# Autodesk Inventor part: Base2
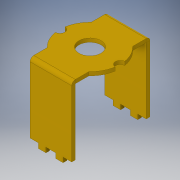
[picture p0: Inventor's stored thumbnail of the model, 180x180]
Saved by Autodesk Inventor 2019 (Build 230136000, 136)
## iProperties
Created: 2019-04
Part Number: Base2
Material: Generic
Document SubType Name: Sheet Metal
Designer: Plo
Density: 1 g/cm^3
Sheet Metal Rule: Default_mm
Appearance: Gold
Author: Plo
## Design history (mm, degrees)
node "Face1"
  sketch "Sketch1"
    geometry: L1 (-8.5, 14.5)-(8.5, 14.5); L2 (-8.5, 8.971)-(-8.5, 14.5); L3 (-8.5, 14.5)-(8.5, -14.5); L4 (8.5, 14.5)-(-8.5, -14.5); L5 (8.5, -8.971)-(8.5, -14.5); L6 (8.5, -14.5)-(-8.5, -14.5); L7 (-8.5, -14.5)-(-8.5, -8.971); L8 (8.5, 14.5)-(8.5, 8.971); C1 r 4.5 at (0, 0); A1 r 2 centre (12.353, -0.059) between (12.206, 1.935) and (12.186, -2.053); A2 r 12.358 centre (0, 0) between (8.5, -8.971) and (12.186, -2.053); A3 r 12.358 centre (0, 0) between (-8.5, 8.971) and (-12.206, 1.935); A4 r 2 centre (-12.353, -0.059) between (-12.186, -2.053) and (-12.206, 1.935); A5 r 12.358 centre (0, 0) between (-12.186, -2.053) and (-8.5, -8.971); A6 r 12.358 centre (0, 0) between (12.206, 1.935) and (8.5, 8.971); 1 further point
    constraints: 16 end point, 12 point on circle, 7 centre point, 5 parallel, 2 perpendicular, 1 coincident, 1 horizontal
    dimensions: "d0" = 17 distance of L3.end L4.end; "d1" = 29 distance of L1.end L3.end; "d2" = 4 diameter of A1; "d3" = 4 diameter of A4; "d17" = 9 diameter of C1
node "Face2"
  sketch "Sketch2"
    geometry: L1 (0, 0)-(17, 0) reference; L2 (0, 0)-(0, -27); L3 (17, 0)-(17, 1.5) reference; L4 (17, -27)-(17, 0); L5 (17, 0)-(0, 0); L6 (6.5, -29)-(6.5, -27); L7 (3.5, -27)-(3.5, -29); L8 (10.5, -29)-(10.5, -27); L9 (13.5, -27)-(13.5, -29); L10 (3.5, -29)-(6.5, -29); L11 (10.5, -29)-(13.5, -29); L12 (0, -27)-(3.5, -27); L13 (6.5, -27)-(10.5, -27); L14 (13.5, -27)-(17, -27); 1 further point
    constraints: 24 end point, 4 perpendicular, 2 vertical
    dimensions: "d7" = 2 distance of L6.start L6.end; "d8" = 3 distance of L6.end L7.start; "d11" = 3 distance of L8.end L9.start
mirror "Mirror1"
sketch "Sketch3"
  geometry: C1 r 4.5 at (0, 0); 1 further point
  constraints: 1 centre point, 1 coincident
  dimensions: "d18" = 9 diameter of C1
cut "Cut1" sketch "Sketch3" dims "d19" = 1.5 (= Thickness), "d20" = 0
body "Solid1"
face "Plate1" dims "d4" = 1.5 (= Thickness)
face "Plate2" dims "d4" = 1.5 (= Thickness), "d12" = 0 (computed from BendRadius), "d13" = 1.5 (= BendReliefWidth), "d15" = 3 (= MinimumRemnant)
bend "Bend1" dims "d4" = 1.5 (= Thickness), "d12" = 0 (computed from BendRadius), "d13" = 1.5 (= BendReliefWidth), "d14" = 0.75 (= BendReliefDepth), "d15" = 3 (= MinimumRemnant), "d16" = 0 (computed from TransitionRadius), "SeamGap" = 0.01
other parameters: "Thickness" = 1.5, "BendRadius" = 0 (derived), "BendReliefWidth" = 1.5 (= Thickness), "BendReliefDepth" = 0.75 (= 0.5 x Thickness), "CornerReliefSize" = 6 (= 4 x Thickness), "MinimumRemnant" = 3 (= 2 x Thickness), "TransitionRadius" = 0 (computed from BendRadius), "JacobiRadiusSize" = 0 (computed from BendRadius), "GapSize" = 1.5 (= Thickness)
